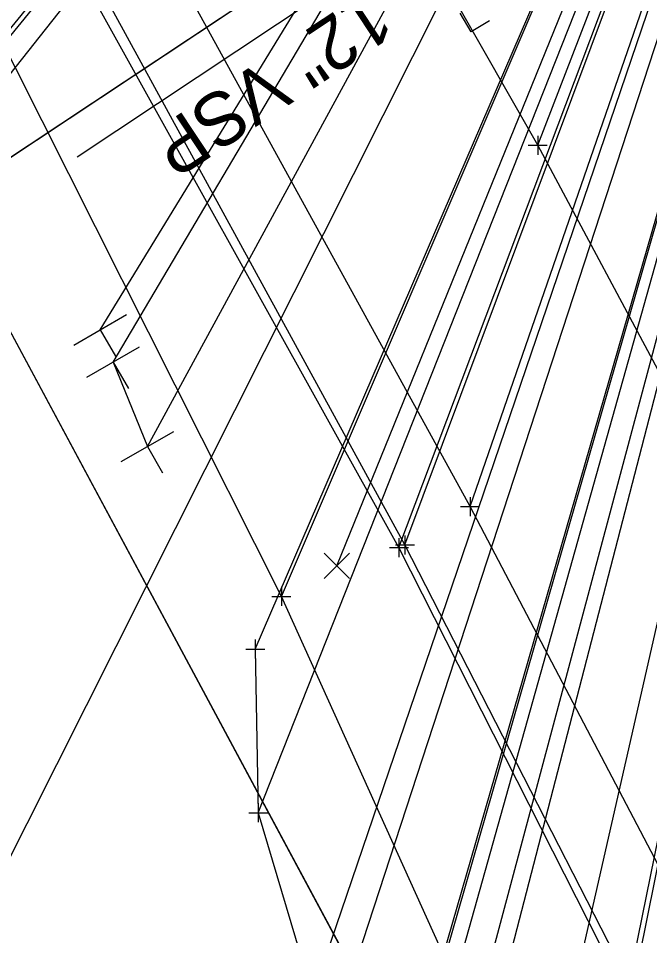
# Model space of a CAD drawing. Extents: x 125846 to 132549, y 511012 to 513420.
# Drawn here: x 126912.03 to 126945.25, y 512204.1 to 512252.39 of the extents above; entities that cross this region are included whole.
import ezdxf

# ---------------------------------------------------------------- set-up
doc = ezdxf.new("R2010")
doc.units = 0
for name, color, linetype in [('Default', 7, 'Continuous'), ('DR_X_Storm_Sewer', 7, 'Continuous'), ('DR_X_Text', 7, 'Continuous'), ('DT_X_Void', 7, 'Continuous'), ('PM_X_CL_Double_Solid', 7, 'Continuous'), ('PM_X_Edge_Line', 7, 'Continuous'), ('PV_X_COP', 7, 'Continuous'), ('PV_X_EOP', 7, 'Continuous'), ('PV_X_Shoulder_Aggregate', 7, 'Continuous'), ('SV_Observation', 7, 'Continuous'), ('SV_X_Break_Lines', 7, 'Continuous'), ('SV_X_Mon_Cells_Found', 7, 'Continuous'), ('UT_X_Overhead_Cable_TV', 7, 'Continuous'), ('UT_X_Overhead_Electric', 7, 'Continuous'), ('UT_X_Overhead_Telecom', 7, 'Continuous'), ('UT_X_Sanitary_Line', 7, 'Continuous'), ('UT_X_Water', 7, 'Continuous')]:
    doc.layers.add(name, color=color, linetype=linetype)

msp = doc.modelspace()

# ---------------------------------------------------------------- linework, layer by layer
at = {"layer": 'Default'}
for points in [[(126950.265, 512270.713), (126896.037, 512234.72)], [(126917.023, 512234.293), (126918.827, 512229.844)]]:
    msp.add_lwpolyline(points, dxfattribs=at)
at = {"layer": 'DR_X_Storm_Sewer'}
msp.add_line((126950.265, 512270.713), (126896.037, 512234.72), dxfattribs=at)
at = {"layer": 'DR_X_Text'}
msp.add_line((126915.118, 512245.104), (126929.953, 512254.951), dxfattribs=at)
at = {"layer": 'DT_X_Void'}
for p, q in [((126914.956, 512235.179), (126917.719, 512236.794)), ((126916.338, 512235.986), (126917.145, 512234.605)), ((126915.639, 512233.489), (126918.406, 512235.096)), ((126917.023, 512234.293), (126917.826, 512232.909)), ((126917.437, 512229.051), (126920.216, 512230.637)), ((126918.827, 512229.844), (126919.62, 512228.455))]:
    msp.add_line(p, q, dxfattribs=at)
at = {"layer": 'PM_X_CL_Double_Solid'}
msp.add_lwpolyline([(126939.361, 512245.706), (126926.53, 512268.202), (126903.606, 512308.715), (126880.31, 512347.953), (126860.082, 512383.784), (126836.45, 512422.705), (126813.369, 512462.311), (126785.218, 512508.842), (126764.444, 512544.164), (126739.794, 512584.777), (126713.112, 512629.687), (126694.803, 512659.525), (126673.403, 512694.562), (126659.778, 512718.869), (126636.017, 512759.401), (126615.052, 512794.202)], dxfattribs=at)
at = {"layer": 'PM_X_Edge_Line'}
msp.add_lwpolyline([(127014.216, 511994.674), (127008.738, 512027.934), (127002.458, 512058.497), (126993.312, 512093.236), (126982.029, 512126.922), (126970.037, 512156.979), (126953.188, 512193.545), (126935.796, 512226.683), (126917.393, 512260.225), (126892.877, 512303.173), (126871.915, 512340.195), (126849.824, 512378.037), (126827.078, 512416.35), (126803.291, 512457.189), (126775.621, 512503.001), (126753.965, 512539.453), (126730.452, 512578.349), (126703.688, 512623.207), (126684.567, 512654.532), (126663.095, 512690.449), (126641.905, 512726.192), (126625.341, 512754.344)], dxfattribs=at)
at = {"layer": 'PV_X_COP'}
msp.add_lwpolyline([(127025.592, 511995.549), (127019.447, 512030.686), (127013.301, 512061.046), (127004.632, 512096.264), (126993.032, 512130.622), (126980.695, 512161.859), (126964.163, 512198.205), (126949.168, 512227.353), (126939.361, 512245.706), (126926.53, 512268.202), (126903.606, 512308.715), (126880.31, 512347.953), (126860.082, 512383.784), (126836.45, 512422.705), (126813.369, 512462.311), (126785.218, 512508.842), (126764.444, 512544.164), (126739.794, 512584.777), (126713.112, 512629.687), (126694.803, 512659.525), (126673.403, 512694.562), (126659.778, 512718.869), (126636.017, 512759.401), (126615.052, 512794.202)], dxfattribs=at)
at = {"layer": 'PV_X_EOP'}
msp.add_lwpolyline([(127009.24, 511994.676), (127003.852, 512026.38), (126997.515, 512058.074), (126988.659, 512091.675), (126977.688, 512125.161), (126966.081, 512154.558), (126949.325, 512191.546), (126932.369, 512224.671), (126914.07, 512258.171), (126888.635, 512302.37), (126868.221, 512337.367), (126845.347, 512376.103), (126823.192, 512414.004), (126798.674, 512454.845), (126771.812, 512500.22), (126749.093, 512537.744), (126726.786, 512574.995), (126699.29, 512620.774), (126681.794, 512650.22), (126658.69, 512688.935), (126637.975, 512724.063), (126621.534, 512752.009)], dxfattribs=at)
at = {"layer": 'PV_X_Shoulder_Aggregate'}
msp.add_lwpolyline([(127001.96, 511993.513), (126995.221, 512024.862), (126988.723, 512057.224), (126979.9, 512089.288), (126975.16, 512101.993), (126973.891, 512105.138), (126967.207, 512120.986), (126955.548, 512150.693), (126941.547, 512187.262), (126925.866, 512221.959), (126909.074, 512255.347), (126883.685, 512300.106), (126862.945, 512334.058), (126844.357, 512365.444), (126840.973, 512368.635), (126839.138, 512371.487), (126839.185, 512375.168), (126816.492, 512410.447), (126794.03, 512452.961), (126773.187, 512490.813), (126746.651, 512537.277)], dxfattribs=at)
at = {"layer": 'SV_Observation'}
for p in [(126894.815, 512231.304), (126897.127, 512233.651), (126900.785, 512235.79), (126910.197, 512205.448), (126916.338, 512235.986), (126917.023, 512234.293), (126918.827, 512229.844), (126920.774, 512181.176), (126924.495, 512219.182), (126924.649, 512210.571), (126925.866, 512221.959), (126928.334, 512198.193), (126928.781, 512223.572), (126929.516, 512186.215), (126929.641, 512186.12), (126932.051, 512224.53), (126932.369, 512224.671), (126933.25, 512195.561), (126933.25, 512195.561), (126933.25, 512195.561), (126933.25, 512195.561), (126935.039, 512195.893), (126935.796, 512226.683), (126936.277, 512196.757), (126938.806, 512190.388), (126939.361, 512245.706), (126939.361, 512245.706), (126940.113, 512181.812), (126941.547, 512187.262)]:
    msp.add_line(p, (126968.531, 512321.464), dxfattribs=at)
at = {"layer": 'SV_X_Break_Lines'}
for points in [[(126999.245, 512048.232), (126997.061, 512058.071), (126988.345, 512091.592), (126977.214, 512124.94), (126965.678, 512154.425), (126948.869, 512191.352), (126932.051, 512224.53), (126913.545, 512257.844), (126888.12, 512302.18), (126867.943, 512337.065), (126844.97, 512375.955), (126822.581, 512413.604), (126798.129, 512454.655), (126771.42, 512499.972), (126748.748, 512537.408)], [(126924.495, 512219.182), (126924.649, 512210.571), (126928.334, 512198.193), (126941.131, 512179.586)]]:
    msp.add_lwpolyline(points, dxfattribs=at)
at = {"layer": 'SV_X_Mon_Cells_Found'}
msp.add_lwpolyline([(126936.825, 512252.253), (126935.861, 512251.68), (126935.275, 512252.665)], dxfattribs=at)
at = {"layer": 'UT_X_Overhead_Cable_TV'}
msp.add_lwpolyline([(127118.017, 511376.722), (127063.55, 511579.79), (127023.043, 511824.951), (126985.21, 512054.96), (126933.25, 512195.561), (126884.628, 512286.174), (126796.707, 512439.393), (126673.508, 512645.419), (126573.76, 512808.402), (126463.864, 512978.437), (126309.686, 513169.014), (126131.861, 513264.581), (125938.03, 513331.206)], dxfattribs=at)
at = {"layer": 'UT_X_Overhead_Electric'}
msp.add_lwpolyline([(127118.017, 511376.722), (127063.55, 511579.79), (127023.043, 511824.951), (126985.21, 512054.96), (126933.25, 512195.561), (126884.628, 512286.174), (126796.707, 512439.393), (126673.508, 512645.419), (126573.76, 512808.402), (126463.864, 512978.437), (126309.686, 513169.014), (126131.861, 513264.581), (125938.03, 513331.206)], dxfattribs=at)
at = {"layer": 'UT_X_Overhead_Telecom'}
msp.add_lwpolyline([(126933.25, 512195.561), (126884.628, 512286.174), (126796.707, 512439.393), (126673.508, 512645.419)], dxfattribs=at)
at = {"layer": 'UT_X_Sanitary_Line'}
for p, q in [((126939.361, 512246.206), (126939.361, 512245.206)), ((126939.361, 512246.206), (126939.361, 512245.206)), ((126938.861, 512245.706), (126939.861, 512245.706)), ((126938.861, 512245.706), (126939.861, 512245.706)), ((126939.361, 512245.706), (126939.361, 512245.706)), ((126939.361, 512245.706), (126939.361, 512245.706)), ((126935.796, 512227.183), (126935.796, 512226.183)), ((126935.296, 512226.683), (126936.296, 512226.683)), ((126935.796, 512226.683), (126935.796, 512226.683)), ((126932.369, 512225.171), (126932.369, 512224.171)), ((126931.869, 512224.671), (126932.869, 512224.671)), ((126932.051, 512225.03), (126932.051, 512224.03)), ((126932.369, 512224.671), (126932.369, 512224.671)), ((126931.551, 512224.53), (126932.551, 512224.53)), ((126932.051, 512224.53), (126932.051, 512224.53)), ((126925.866, 512222.459), (126925.866, 512221.459)), ((126925.366, 512221.959), (126926.366, 512221.959)), ((126925.866, 512221.959), (126925.866, 512221.959)), ((126924.495, 512219.682), (126924.495, 512218.682)), ((126923.995, 512219.182), (126924.995, 512219.182)), ((126924.495, 512219.182), (126924.495, 512219.182)), ((126924.649, 512211.071), (126924.649, 512210.071)), ((126924.149, 512210.571), (126925.149, 512210.571)), ((126924.649, 512210.571), (126924.649, 512210.571))]:
    msp.add_line(p, q, dxfattribs=at)
at = {"layer": 'UT_X_Water'}
for p, q in [((126928.115, 512222.904), (126929.448, 512224.239)), ((126928.115, 512224.239), (126929.448, 512222.904))]:
    msp.add_line(p, q, dxfattribs=at)

# ---------------------------------------------------------------- texts
at = {"layer": 'DR_X_Text'}
msp.add_text('12" VSP', height=2.8, rotation=213.574, dxfattribs=at).set_placement((126930.467, 512253.97))

doc.saveas('drawing.dxf')
